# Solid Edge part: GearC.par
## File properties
Author: Chalangana Oshan
Template: iso metric part.par
Last saved by: Nimesh.N
Revision: 39
Application: Solid Edge
Density: 7250.000 kg/m^3
Accuracy: 0.990
Username: Nimesh.N
Material: Iron:0.6025 , EN-GJL-250
Face Style: Gray
Fill Style: ANSI31(Iron)
Grouping: Iron\Gray Cast Iron
LibraryName: Materials-DIN
Coef. of Thermal Exp: 1.05e-05
Thermal Conductivity: 58.0
Specific Heat: 460.0
Modulus of Elasticity: 120000003072.0
Poisson's Ratio: 0.26
Yield Stress: 165593984.0
Ultimate Stress: 250000000.0
Elongation: 0.0
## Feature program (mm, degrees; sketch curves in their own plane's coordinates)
sketch for "unnamed Protrusion 1" plane through (0, 0, 0) normal (0, 0, 1) x-axis (1, 0, 0)
  circle centre (0, 0) radius 115
extrude "unnamed Protrusion 1" add finite 130 along -normal
sketch used by "unnamed Cutout 1" plane through (0, 0, 0) normal (0, 0, 1) x-axis (1, 0, 0)
  line (0, 0) -> (-17.1399, 113.7155)
  line (0, 0) -> (-14.2995, 114.1075)
  line (0, 0) -> (-19.9695, 113.2529)
  line (-3.4587, 92.4353) -> (3.4587, 92.4353)
  arc centre (-61.4345, 76.9822) radius 60 from (-14.2995, 114.1075) to (-3.4587, 92.4353) cw
  arc centre (61.4345, 76.9822) radius 60 from (14.2995, 114.1075) to (3.4587, 92.4353) ccw
extrude "unnamed Cutout 1" cut through along -normal
pattern "unnamed Pattern 1" of "unnamed Cutout 1"
pattern "unnamed Pattern 2"
sketch for "ExtrudedProtrusion_2" plane through (0, -0.4462, 0) normal (0, 0, 1) x-axis (0.07473, 0.997204, 0)
extrude "ExtrudedProtrusion_2" add finite 16 along +normal
sketch for "unnamed Cutout 2" plane through (0, 0, 16) normal (0, 0, 1) x-axis (0, 1, 0)
extrude "unnamed Cutout 2" cut through along -normal
sketch for "unnamed Cutout 3" plane through (0, 0, 16) normal (0, 0, 1) x-axis (0, 1, 0)
extrude "unnamed Cutout 3" cut through along -normal
Other named dimensions: "ExtrudedSurface_3": FiniteDepth = 130 mm
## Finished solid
Body 1: sheet body, 1 face, 2 edges, 0 vertices.
  Faces by surface: cylinder 1
  Edges by curve: circle 2
Body 2: solid body, 90 faces, 264 edges, 176 vertices.
  Faces by surface: cylinder 64, plane 26
  Edges by curve: line 136, circle 128
Bounding box of the edges (mm): 229.714 x 229.107 x 130.000, from (-114.857, -115, -130) to (114.857, 114.1075, 0).
Cylindrical faces by radius (mm): R36 x1, R60 x42, R105 x1, R115 x21
Planar faces by outward normal: +x 1, +y 2, +z 1, -y 1, -z 1, oblique 20
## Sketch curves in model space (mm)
line (0, 0, 0) -> (-19.9695, 113.2529, 0)
line (0, 0, 0) -> (-17.1399, 113.7155, 0)
line (0, 0, 0) -> (4.3, 114.9196, 0)
line (0, 0, 0) -> (-4.3, 114.9196, 0)
arc centre (61.4345, 76.9822, 0) radius 60 from (14.2995, 114.1075, 0) through (7.7736, 103.8244, 0) to (3.4587, 92.4353, 0)
line (-3.4587, 92.4353, 0) -> (3.4587, 92.4353, 0)
arc centre (-61.4345, 76.9822, 0) radius 60 from (-14.2995, 114.1075, 0) through (-7.7736, 103.8244, 0) to (-3.4587, 92.4353, 0)
line (0, 0, 0) -> (-14.2995, 114.1075, 0)
circle centre (0, 0, 0) radius 115
circle centre (0, 0, 0) radius 105
circle centre (0, 0, 0) radius 92.5
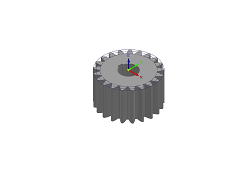
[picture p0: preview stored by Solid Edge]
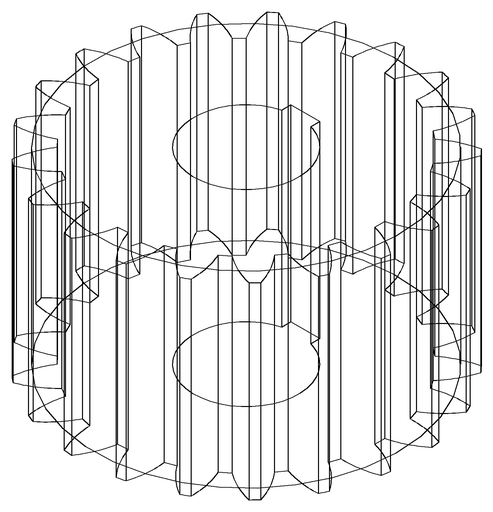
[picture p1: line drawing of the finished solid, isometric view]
